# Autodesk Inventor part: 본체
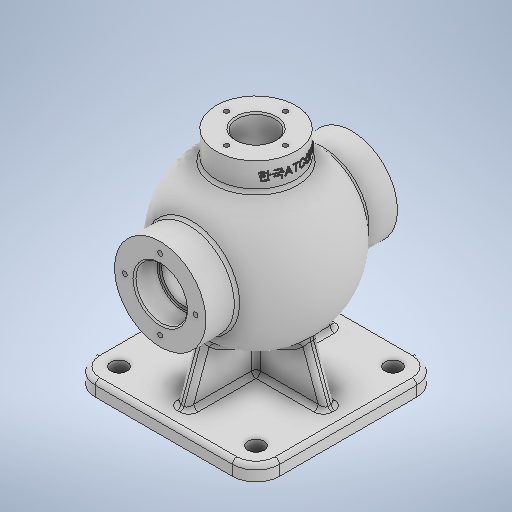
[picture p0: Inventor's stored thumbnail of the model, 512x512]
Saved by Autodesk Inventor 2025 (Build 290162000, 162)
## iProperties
Created: 2024-07
Part Number: 본체
Material: 일반
Document SubType Name: Modeling
Designer: parkm
Density: 1 g/cm^3
Appearance: 기본값
Author: parkm
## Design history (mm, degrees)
sketch "스케치1"
  geometry: L1 (62.5, 62.5)-(-62.5, 62.5); L2 (-62.5, 62.5)-(-62.5, -62.5); L3 (-62.5, -62.5)-(62.5, -62.5); L4 (62.5, -62.5)-(62.5, 62.5); L5 (62.5, 62.5)-(-62.5, -62.5); L6 (-62.5, 62.5)-(62.5, -62.5); 1 further point
  constraints: 12 end point, 2 midpoint, 2 parallel, 1 horizontal, 1 perpendicular
  dimensions: "d0" = 125 distance of L2.end L3.end; "d1" = 125 distance of L1.end L2.end
extrude "돌출1" new body sketch "스케치1" distance "d2" = 10; taper "d3" = 0 deg
fillet "모깎기1" dims "d4" = 16
sketch "스케치2"
  geometry: L1 (-46.5, 0)-(46.5, 0) reference; L2 (0, 144.733)-(0, 0); A1 r 54 centre (0, 85) between (0, 31) and (0, 139); 2 further points
  constraints: 2 end point, 2 midpoint, 2 point on circle, 2 point on line, 1 centre point, 1 vertical, 1 vertical alignment
  dimensions: "d5" = 108 diameter of A1; "d6" = 85 distance of L2.end A1.centre
revolve "회전1" sketch "스케치2" stored, may be unused: angle "d7" = 90 deg
sketch "스케치3"
  geometry: L1 (50, 35.941)-(10, 50.5); L2 (10, 62.5)-(10, 46.5) reference; L3 (0, 62.5)-(10, 62.5) reference; L4 (0, 0)-(175.833, 0); L5 (50, -35.941)-(10, -50.5); L6 (10, 50.5)-(10, -50.5); L7 (10, -46.5)-(10, 46.5) reference; L8 (10, -62.5)-(0, -62.5) reference; A1 r 57.102 centre (94.372, 0) between (50, 35.941) and (71.299, -52.233); 6 further points
  constraints: 8 end point, 2 point on circle, 2 point on line, 2 symmetric about line, 1 centre point, 1 collinear, 1 equal length, 1 horizontal, 1 midpoint, 2 other
  dimensions: "d8" = 12 vertical distance of point (5, 62.5) L1.end; "d9" = 20 deg angle of L1 L3; "d13" = 20 deg angle of L5 L8; "d14" = 40 horizontal distance of L1.start L1.end
extrude "돌출2" join sketch "스케치3" stored distance "d11" = 8; taper "d12" = 0 deg
sketch "스케치4"
  geometry: L1 (-30.003, 66.314)-(-50.5, 10); L2 (30.003, 66.314)-(50.5, 10); L3 (-62.5, 10)-(-46.5, 10) reference; L4 (46.5, 10)-(62.5, 10) reference; L5 (-62.5, 0)-(-62.5, 10) reference; L6 (62.5, 10)-(62.5, 0) reference; L7 (-50.5, 10)-(50.5, 10); A1 r 46.287 centre (0, 101.56) between (-30.003, 66.314) and (30.003, 66.314); 3 further points
  constraints: 6 end point, 2 point on circle, 2 point on line, 1 centre point, 1 collinear, 1 equal length
  dimensions: "d15" = 12 distance from line of L1.end L5; "d16" = 12 distance from line of L2.end L6; "d17" = 20 deg angle of L1 L5; "d18" = 20 deg angle of L2 L6
extrude "돌출3" join sketch "스케치4" stored distance "d19" = 8; taper "d20" = 0 deg
fillet "모깎기2" dims "d21" = 3
fillet "모깎기3" dims "d22" = 3
fillet "모깎기4" dims "d23" = 3
fillet "모깎기5" dims "d24" = 3
sketch "스케치5"
  geometry: C1 r 31 at (0, 85); A1 r 54 centre (0, 85) between (38.709, 47.349) and (-38.709, 47.349) reference; 1 further point
  constraints: 1 centre point, 1 concentric
  dimensions: "d25" = 62 diameter of C1
extrude "돌출4" join sketch "스케치5" stored distance "d26" = 130; taper "d27" = 0 deg
fillet "모깎기6" dims "d28" = 3
node "작업 평면1"
sketch "스케치6"
  geometry: C1 r 27 at (0, 0); 1 further point
  constraints: 1 centre point, 1 coincident
  dimensions: "d30" = 54 diameter of C1
extrude "돌출5" join sketch "스케치6" distance "d31" = 30; taper "d32" = 0 deg
fillet "모깎기7" dims "d33" = 3
sketch "스케치8"
  geometry: L1 (0, 0)-(0, 160.102); A1 r 44 centre (0, 85) between (0, 41) and (0, 129); A2 r 54 centre (0, 85) between (38.709, 47.349) and (-38.709, 47.349) reference
  constraints: 2 end point, 2 point on circle, 2 point on line, 1 centre point, 1 concentric, 1 vertical
  dimensions: "d34" = 88 diameter of A1
revolve "회전2" sketch "스케치8" stored, may be unused: angle "d39" = 90 deg
sketch "스케치9"
  geometry: C1 r 31 at (0, 0) reference; C2 r 17.5 at (0, 0); 1 further point
  constraints: 1 centre point, 1 coincident
  dimensions: "d40" = 35 diameter of C2
extrude "돌출6" cut sketch "스케치9" distance "d41" = 16; taper "d42" = 0 deg
sketch "스케치10"
  geometry: C1 r 17.5 at (0, 0) reference; 1 further point
extrude "돌출7" cut sketch "스케치10" distance "d43" = 16; taper "d44" = 0 deg
sketch "스케치11"
  geometry: C1 r 17.5 at (0, 0) reference; C2 r 15 at (0, 0); 1 further point
  constraints: 1 centre point, 1 coincident
  dimensions: "d45" = 30 diameter of C2
extrude "돌출8" cut sketch "스케치11" extent not by distance; stored distance "d46" = 0; taper "d47" = 0 deg
sketch "스케치12"
  geometry: C1 r 13 at (0, 0); 1 further point
  constraints: 1 centre point, 1 coincident
  dimensions: "d48" = 26 diameter of C1
extrude "돌출9" cut sketch "스케치12" stored distance "d49" = 10; taper "d50" = 0 deg
chamfer "모따기1" distance "d51" = 1; stored, may be unused: second distance "d52" = 2, angle "d53" = 45 deg
fillet "모깎기8" dims "d54" = 0.6
sketch "스케치13"
  geometry: L1 (-70.97, 0)-(83.117, 0); L2 (0, 46.873)-(0, -34.996); C1 r 31 at (0, 0) reference; A1 r 24 centre (0, 0) between (0, 24) and (-24, 0); 3 further points
  constraints: 6 point on line, 4 end point, 4 point on circle, 1 centre point, 1 concentric, 1 horizontal, 1 vertical
  dimensions: "d55" = 48 diameter of A1
hole "구멍1" sketch "스케치13" at (0, 24), (-24, 0), (0, -24), (24, 0) diameter "d56" = 3.242; stored, may be unused: countersink angle "d60" = 90 deg, drill point angle "d62" = 120 deg; dims "d57" = 12, "d58" = 4, "d59" = 2, "d61" = 15
sketch "스케치14"
  geometry: C1 r 1.621 at (-24, 0) reference; C2 r 1.621 at (0, 24) reference; C3 r 1.621 at (24, 0) reference; C4 r 1.621 at (0, -24) reference; 1 further point
hole "구멍2" sketch "스케치14" at (0, 24), (-24, 0), (0, -24), (24, 0) diameter "d63" = 3.242; stored, may be unused: countersink angle "d67" = 90 deg, drill point angle "d69" = 120 deg; dims "d64" = 12, "d65" = 4, "d66" = 2, "d68" = 15
sketch "스케치15"
  geometry: L1 (-105.545, 0)-(92.862, 0); L2 (0, 73.134)-(0, -31.988); A1 r 20 centre (0, 0) between (0, 20) and (-20, 0); 3 further points
  constraints: 5 point on line, 4 end point, 4 point on circle, 1 centre point, 1 coincident, 1 horizontal, 1 vertical
  dimensions: "d70" = 40 diameter of A1
hole "구멍3" sketch "스케치15" at (0, 20), (-20, 0), (20, 0), (0, -20) diameter "d71" = 3.242; stored, may be unused: countersink angle "d75" = 90 deg, drill point angle "d77" = 120 deg; dims "d72" = 9, "d73" = 4, "d74" = 2, "d76" = 11
sketch "스케치16"
  geometry: A1 r 13 centre (46.5, -46.5) between (46.5, -59.5) and (59.5, -46.5) reference; A2 r 13 centre (46.5, 46.5) between (59.5, 46.5) and (46.5, 59.5) reference; A3 r 13 centre (-46.5, -46.5) between (-59.5, -46.5) and (-46.5, -59.5) reference; A4 r 13 centre (-46.5, 46.5) between (-46.5, 59.5) and (-59.5, 46.5) reference; 5 further points
  constraints: 4 coincident
hole "구멍4" sketch "스케치16" at (46.5, -46.5), (46.5, 46.5), (-46.5, -46.5), (-46.5, 46.5) diameter "d78" = 11; stored, may be unused: countersink angle "d82" = 90 deg, drill point angle "d84" = 0 deg; dims "d79" = 9, "d80" = 4, "d81" = 2, "d83" = 11
node "작업 평면2"
sketch "스케치17"
  geometry: L1 (150, -27)-(150, 27) reference; L2 (0, 0)-(196.455, 0); 1 further point
  constraints: 2 end point, 1 horizontal, 1 point on line, 1 other
  dimensions: "d86" = 9 distance from line of point (141, 0) L1
feature "엠보싱1" sketch "스케치17" dims "d0" = 125, "d1" = 125, "d87" = 0.5, "d88" = 0
node "솔리드1"
node "투영된 루프1"
feature "A9D066F2-1C7D-4E18-AEED-F7BC21143FA4" dims "d78" = 11, "d79" = 9, "d80" = 4, "d81" = 2, "d82" = 90 deg, "d83" = 11, "d84" = 0
other parameters: "d35" = 0.5, "d36" = 2, "d37" = 0, "d85" = 27
